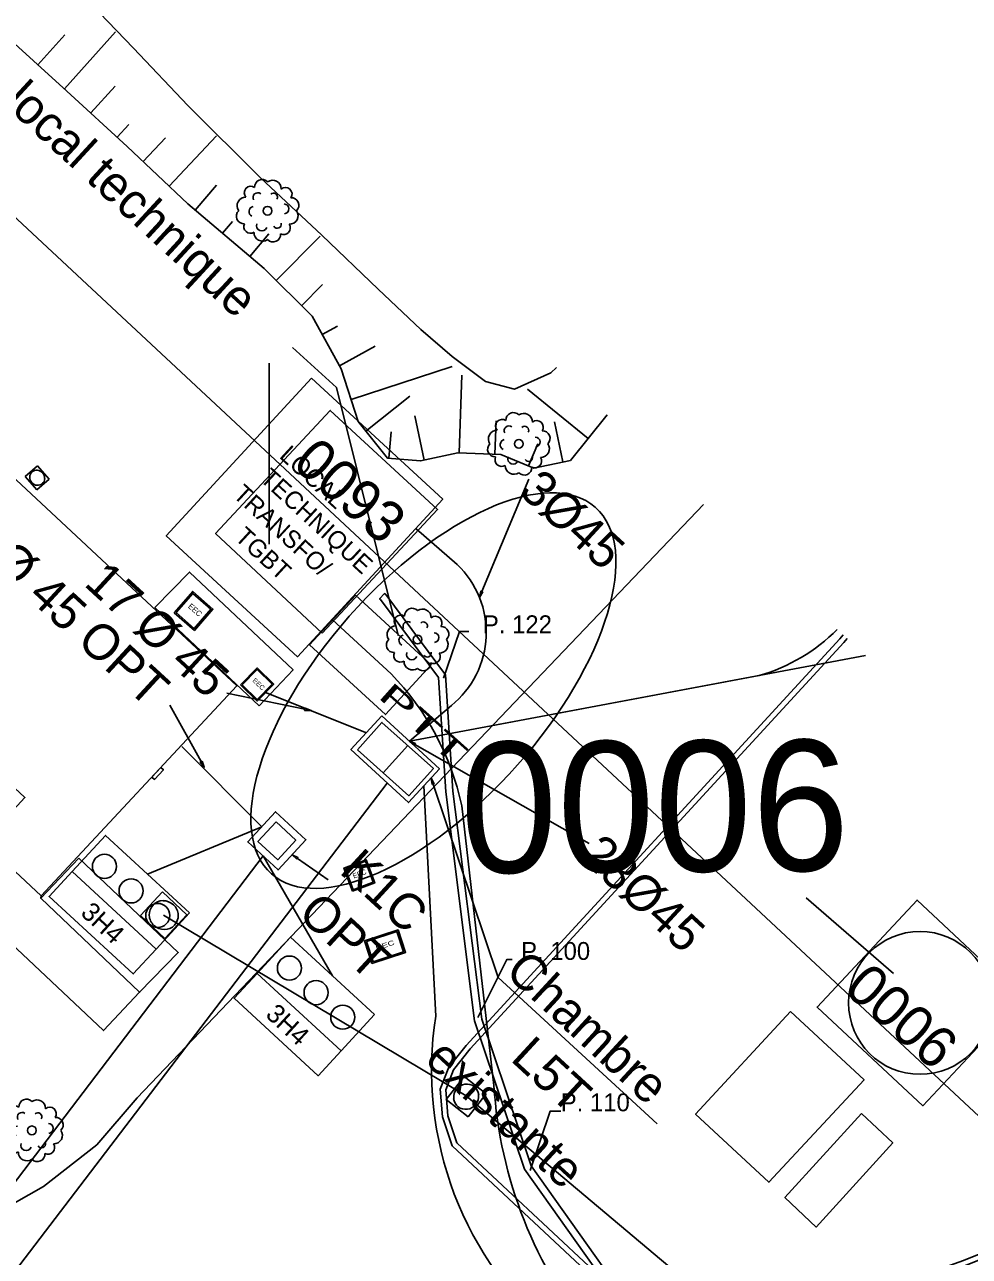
# Model space of a CAD drawing. Extents: x 343997 to 344255, y 298512 to 298767.
# Drawn here: x 344165.08 to 344191.53, y 298671.53 to 298706.03 of the extents above; entities that cross this region are included whole.
import ezdxf

# ---------------------------------------------------------------- set-up
doc = ezdxf.new("R2010")
doc.units = 0
for name, color, linetype in [('Commentaires', 7, 'Continuous'), ('Default', 7, 'Continuous'), ('DH_CADRE -CARTOUCHE', 7, 'Continuous'), ('DH_CADRE-CARTOUCHE', 7, 'Continuous'), ('DH_CADRE-CARTOUCHE-NORD', 7, 'Continuous'), ('DH_NORD', 7, 'Continuous'), ('DH_TEXTE', 7, 'Continuous'), ('DIR-Projet VRD1', 7, 'Continuous'), ('EDE - VRD - O-DONNEE', 7, 'Continuous'), ('EL-coffret', 7, 'Continuous'), ('EL-FOURR', 7, 'Continuous'), ('EL-GC', 7, 'Continuous'), ('EL-Projet VRD HTA', 7, 'Continuous'), ('GO_DALLE', 7, 'Continuous'), ('MT-DONNEE', 7, 'Continuous'), ('MT-TRANS', 7, 'Continuous'), ('O-Projet New VRD', 7, 'Continuous'), ('OPT chambre', 7, 'Continuous'), ('OPT texte', 7, 'Continuous'), ('OPT VRD', 7, 'Continuous'), ('PC_REBAR', 7, 'Continuous'), ('PS_OBJECT', 7, 'Continuous'), ('PS_PLATE', 7, 'Continuous'), ('RES_EAU PLUVIALE', 7, 'Continuous'), ('RES_ELECTRICITE', 7, 'Continuous'), ('RES_MOYENNE TENSION', 7, 'Continuous')]:
    doc.layers.add(name, color=color, linetype=linetype)

# ---------------------------------------------------------------- blocks, each defined once
blk = doc.blocks.new('CT2')
at = {"layer": 'Default'}
blk.add_lwpolyline([(0, 0), (0.1, 0), (0.1, 0.1), (0, 0.1)], close=True, dxfattribs=at)
blk.add_lwpolyline([(0.05, 0.1), (0.05, 0)], dxfattribs=at)
blk.add_text('PTT', height=0.06, dxfattribs=at).set_placement((-0.03, 0.1425))
blk = doc.blocks.new('REG_INC')
at = {"layer": 'Default'}
for p, q in [((0, 0.1), (0.1, 0.1)), ((0, 0), (0, 0.1)), ((0.1, 0.1), (0.1, 0)), ((0.1, 0), (0, 0))]:
    blk.add_line(p, q, dxfattribs=at)
for centre, start, end in [((0.0498, 0.05), 135.0055, 180.0055), ((0.05, 0.0498), 90.0058, 135.0058), ((0.05, 0.05), 45.0069, 90.0069), ((0.0499, 0.0499), 0.0066, 45.0066), ((0.0501, 0.05), 180.0066, 225.0066), ((0.0501, 0.0499), 315.0055, 0.0055), ((0.0499, 0.0498), 225.0069, 270.0069), ((0.0499, 0.05), 270.0058, 315.0058)]:
    blk.add_arc(centre, 0.044, start, end, dxfattribs=at)
blk = doc.blocks.new('RES_ELECTRICITE')
at = {"layer": 'RES_ELECTRICITE'}
for points in [[(0, 0), (0, 0.1), (0.1, 0.1), (0.1, 0)], [(0.005, 0.005), (0.005, 0.095), (0.095, 0.095), (0.095, 0.005)]]:
    blk.add_lwpolyline(points, close=True, dxfattribs=at)
blk.add_text('EEC', height=0.02, dxfattribs=at).set_placement((0.0237, 0.046))
blk = doc.blocks.new('ARB1')
at = {"layer": 'Default'}
blk.add_circle((0, 0), 0.0122, dxfattribs=at)
for centre, radius, start, end in [((-0.0153, 0.0664), 0.0211, 43.6925, 183.5969), ((0.0139, 0.0613), 0.0241, 358.4583, 125.1928), ((-0.0613, 0.0139), 0.0241, 88.4583, 215.1928), ((-0.0471, 0.0503), 0.0183, 53.9554, 222.2066), ((-0.0276, 0.037), 0.0134, 52.4396, 209.5496), ((0.0164, 0.038), 0.0112, 330.5895, 133.7127), ((0.0501, 0.0468), 0.0183, 325.1444, 131.0175), ((0.0664, 0.0153), 0.0211, 313.6925, 93.5969), ((-0.0373, -0.0024), 0.0149, 103.7092, 242.3465), ((0.0458, 0.0052), 0.0137, 276.6214, 88.967), ((0.0613, -0.0139), 0.0241, 268.4583, 35.1928), ((-0.0664, -0.0153), 0.0211, 133.6925, 273.5969), ((-0.0478, -0.0443), 0.019, 155.2243, 300.9377), ((-0.0139, -0.0613), 0.0241, 178.4583, 305.1928), ((-0.0163, -0.042), 0.0148, 159.5371, 338.1663), ((0.0153, -0.0664), 0.0211, 223.6925, 3.5969), ((0.0271, -0.038), 0.0112, 210.5895, 13.7127), ((0.0448, -0.0483), 0.0188, 243.1323, 33.0297)]:
    blk.add_arc(centre, radius, start, end, dxfattribs=at)
blk = doc.blocks.new('K1C')
at = {"layer": 'Default'}
for points in [[(35083.6085, 29821.5636), (35083.7239, 29821.5636), (35083.7239, 29821.6785), (35083.6085, 29821.6785)], [(35083.6287, 29821.6586), (35083.7037, 29821.6586), (35083.7037, 29821.5836), (35083.6287, 29821.5836)]]:
    blk.add_lwpolyline(points, close=True, dxfattribs=at)
for points in [[(35083.7037, 29821.6586), (35083.7039, 29821.6585)], [(35083.6085, 29821.5637), (35083.6087, 29821.5636)]]:
    blk.add_lwpolyline(points, dxfattribs=at)
blk = doc.blocks.new('_U58')
at = {"layer": 'EDE - VRD - O-DONNEE'}
for points in [[(0.01067, 0.01553), (-0.01067, 0.01553), (-0.01067, 0.00632), (0.01067, 0.00632)], [(-0.01067, 0.00632), (0.01067, 0.00632), (0.01067, 0), (-0.01067, 0)]]:
    blk.add_lwpolyline(points, close=True, dxfattribs=at)
for centre in [(-0.00689, 0.01114), (-0.00013, 0.01114), (0.00664, 0.01114)]:
    blk.add_circle(centre, 0.00225, dxfattribs=at)
blk.add_text('3H4', height=0.0035, dxfattribs=at).set_placement((-0.00426, 0.00143))

msp = doc.modelspace()

# ---------------------------------------------------------------- linework, layer by layer
at = {"layer": 'Commentaires'}
for points in [[(344173.808, 298695.861), (344172.584, 298696.987)], [(344175.537, 298688.921), (344173.808, 298695.861)]]:
    msp.add_lwpolyline(points, dxfattribs=at)
msp.add_lwpolyline([(344175.537, 298688.921), (344175.537, 298688.92), (344175.537, 298688.921)], close=True, dxfattribs=at)
msp.add_ellipse((344176.525, 298687.373), major_axis=(4.533, 5.134), ratio=0.458958, dxfattribs=at)
at = {"layer": 'DH_CADRE -CARTOUCHE'}
for points in [[(343997.309, 298660.673), (344147.183, 298520.807), (344245.09, 298625.72), (344095.215, 298765.586)], [(344193.026, 298678.733), (344190.231, 298675.746), (344187.264, 298678.509), (344190.065, 298681.504)]]:
    msp.add_lwpolyline(points, close=True, dxfattribs=at)
msp.add_circle((344190.148, 298678.625), 2, dxfattribs=at)
at = {"layer": 'DH_CADRE-CARTOUCHE'}
for points in [[(344122.649, 298749.916), (344119.175, 298746.216), (344104.333, 298729.921), (344103.629, 298728.425), (344103.178, 298726.908), (344102.994, 298725.349), (344103.009, 298724.152), (344103.293, 298722.366), (344103.622, 298721.156), (344104.336, 298719.642), (344105.154, 298718.475), (344128.542, 298697.099), (344156.76, 298672.229), (344158.923, 298671.699), (344160.816, 298671.605), (344163.478, 298672.279), (344165.611, 298673.484), (344167.1, 298674.65), (344168.229, 298675.97), (344184.084, 298692.584)], [(344188, 298688.93), (344187.902, 298688.824), (344177.441, 298677.433), (344176.96, 298676.824), (344176.719, 298676.211), (344176.783, 298675.437), (344177.049, 298674.626), (344182.208, 298669.797), (344182.64, 298669.601), (344183.285, 298669.47), (344184.88, 298669.638), (344186.656, 298669.899), (344187.783, 298670.119), (344189.007, 298670.475), (344190.164, 298670.82), (344191.42, 298671.271), (344192.391, 298671.666), (344193.259, 298672.085), (344195.097, 298672.911), (344197.862, 298674.128), (344198.708, 298674.569), (344199.685, 298675.181), (344198.697, 298676.128)], [(344188.109, 298688.828), (344188.012, 298688.722), (344177.555, 298677.336), (344177.092, 298676.749), (344176.872, 298676.188), (344176.931, 298675.467), (344177.18, 298674.709), (344182.292, 298669.924), (344182.687, 298669.745), (344183.293, 298669.621), (344184.862, 298669.787), (344186.631, 298670.046), (344187.747, 298670.264), (344188.964, 298670.619), (344190.117, 298670.962), (344191.366, 298671.411), (344192.331, 298671.803), (344193.196, 298672.221), (344195.036, 298673.048), (344197.797, 298674.263), (344198.633, 298674.699), (344199.442, 298675.206), (344198.593, 298676.019), (344198.697, 298676.128)]]:
    msp.add_lwpolyline(points, dxfattribs=at)
at = {"layer": 'DH_CADRE-CARTOUCHE-NORD'}
for points in [[(344166.599, 298682.682), (344169.384, 298680.035), (344168.3, 298678.926), (344165.531, 298681.558)], [(344166.599, 298682.682), (344165.531, 298681.558)], [(344237.935, 298621.298), (344195.027, 298661.228), (344177.442, 298676.027), (344168.974, 298681.087)]]:
    msp.add_lwpolyline(points, dxfattribs=at)
at = {"layer": 'DH_TEXTE'}
for p, q in [((344171.924, 298696.541), (344171.924, 298691.473)), ((344186.963, 298681.569), (344189.41, 298679.451))]:
    msp.add_line(p, q, dxfattribs=at)
at = {"layer": 'DIR-Projet VRD1'}
for p, q in [((344188.618, 298688.353), (344175.853, 298685.953)), ((344175.853, 298685.953), (344185.645, 298687.794)), ((344175.232, 298684.784), (344162.44, 298668.004))]:
    msp.add_line(p, q, dxfattribs=at)
for points in [[(344176.047, 298691.903), (344177.193, 298690.9)], [(344174.649, 298686.191), (344171.827, 298687.323)], [(344177.029, 298686.955), (344175.853, 298685.953)], [(344176.26, 298684.707), (344176.591, 298678.258)]]:
    msp.add_lwpolyline(points, dxfattribs=at)
for centre, radius, start, end in [((344175.379, 298689), 2.627, 308.9097, 46.3418), ((344184.276, 298692.607), 5.003, 285.8756, 315.2875), ((344186.231, 298676.743), 9.758, 171.0714, 230.5902)]:
    msp.add_arc(centre, radius, start, end, dxfattribs=at)
at = {"layer": 'EL-coffret'}
msp.add_lwpolyline([(344168.896, 298685.223), (344168.968, 298685.156), (344168.718, 298684.884), (344168.645, 298684.951)], close=True, dxfattribs=at)
at = {"layer": 'EL-FOURR'}
msp.add_lwpolyline([(344182.92, 298668.55), (344179.08, 298673.97), (344177.68, 298678.12), (344176.87, 298684.54), (344176.67, 298687.74), (344175.04, 298689.92), (344175.02, 298689.94), (344175.16, 298690.09), (344175.19, 298690.06), (344176.86, 298687.81), (344177.07, 298684.56), (344177.88, 298678.17), (344179.26, 298674.06), (344183.08, 298668.68)], dxfattribs=at)
at = {"layer": 'EL-GC'}
msp.add_lwpolyline([(344173.11, 298696.12), (344176.789, 298692.734), (344172.725, 298688.319), (344169.046, 298691.706)], close=True, dxfattribs=at)
at = {"layer": 'EL-Projet VRD HTA'}
msp.add_lwpolyline([(344174.342, 298690.05), (344176.465, 298688.096), (344175.183, 298686.703), (344173.06, 298688.657)], close=True, dxfattribs=at)
at = {"layer": 'GO_DALLE'}
msp.add_lwpolyline([(344165.544, 298681.621), (344165.531, 298681.558), (344168.3, 298678.926), (344167.289, 298677.848), (344153.365, 298690.972), (344139.141, 298704.253), (344140.184, 298705.334)], dxfattribs=at)
for points in [[(344171.646, 298686.945), (344168.73, 298689.7), (344169.697, 298690.692), (344172.598, 298687.952)], [(344186.526, 298678.381), (344188.581, 298676.471), (344185.918, 298673.601), (344183.863, 298675.512)], [(344188.509, 298675.532), (344189.384, 298674.705), (344187.243, 298672.345), (344186.368, 298673.172)]]:
    msp.add_lwpolyline(points, close=True, dxfattribs=at)
at = {"layer": 'MT-DONNEE'}
for points in [[(344176.81, 298687.72), (344177.26, 298689.03), (344177.52, 298689.03)], [(344177.77, 298678.22), (344178.58, 298679.84), (344178.73, 298679.84)], [(344179.23, 298673.93), (344179.79, 298675.59), (344180.09, 298675.59)]]:
    msp.add_lwpolyline(points, dxfattribs=at)
at = {"layer": 'MT-TRANS'}
msp.add_lwpolyline([(344173.412, 298688.979), (344170.426, 298691.775), (344173.636, 298695.222), (344176.642, 298692.441)], close=True, dxfattribs=at)
at = {"layer": 'O-Projet New VRD'}
for points in [[(344177.885, 298690.149), (344179.199, 298693.297)], [(344172.924, 298686.849), (344170.744, 298687.299)], [(344176.009, 298685.864), (344180.887, 298683.091)], [(344176.517, 298684.754), (344178.341, 298679.334)], [(344178.341, 298679.334), (344182.793, 298675.235)]]:
    msp.add_lwpolyline(points, dxfattribs=at)
for points in [[(344177.913, 298690.138), (344177.816, 298689.983), (344177.857, 298690.161)], [(344172.931, 298686.878), (344173.101, 298686.812), (344172.918, 298686.819)], [(344175.083, 298686.662), (344176.694, 298685.178), (344175.827, 298684.237), (344174.216, 298685.72)], [(344175.994, 298685.838), (344175.853, 298685.953), (344176.024, 298685.89)], [(344176.489, 298684.744), (344176.46, 298684.924), (344176.546, 298684.763)]]:
    msp.add_lwpolyline(points, close=True, dxfattribs=at)
at = {"layer": 'OPT chambre'}
msp.add_lwpolyline([(344172.674, 298683.188), (344172.675, 298683.186)], dxfattribs=at)
at = {"layer": 'OPT texte'}
for points in [[(344170.025, 298685.383), (344169.144, 298686.96)], [(344168.523, 298682.234), (344171.72, 298683.556)], [(344173.701, 298679.385), (344171.755, 298682.743)], [(344172.717, 298682.673), (344173.581, 298682.076)]]:
    msp.add_lwpolyline(points, dxfattribs=at)
for points in [[(344170.051, 298685.398), (344170.112, 298685.226), (344169.998, 298685.369)], [(344172.7, 298682.648), (344172.568, 298682.775), (344172.734, 298682.697)]]:
    msp.add_lwpolyline(points, close=True, dxfattribs=at)
at = {"layer": 'OPT VRD'}
msp.add_line((344171.72, 298683.556), (344169.486, 298685.809), dxfattribs=at)
msp.add_lwpolyline([(344171.755, 298682.743), (344159.176, 298666.214)], dxfattribs=at)
at = {"layer": 'PS_OBJECT'}
for p, q in [((344166.194, 298704.228), (344167.63, 298705.819)), ((344165.452, 298704.899), (344166.207, 298705.736)), ((344166.931, 298703.552), (344167.62, 298704.301)), ((344167.668, 298702.875), (344167.995, 298703.231)), ((344168.398, 298702.192), (344169.029, 298702.858)), ((344169.124, 298701.504), (344170.456, 298702.91)), ((344169.86, 298700.827), (344170.455, 298701.528)), ((344170.623, 298700.18), (344170.905, 298700.513)), ((344171.385, 298699.533), (344171.922, 298700.165)), ((344172.123, 298698.858), (344173.356, 298700.101)), ((344172.833, 298698.154), (344173.419, 298698.744)), ((344173.41, 298697.349), (344173.837, 298697.584)), ((344173.893, 298696.473), (344174.893, 298697.024)), ((344174.22, 298695.529), (344177.051, 298696.448)), ((344177.249, 298694.03), (344177.324, 298696.208)), ((344180.856, 298694.434), (344179.157, 298695.812)), ((344174.638, 298694.637), (344175.866, 298695.615)), ((344176.27, 298693.827), (344176.001, 298695.073)), ((344178.249, 298693.996), (344178.281, 298694.927)), ((344180.152, 298693.778), (344179.912, 298694.904)), ((344175.276, 298693.882), (344175.34, 298694.624)), ((344179.184, 298693.667), (344179.445, 298694.288))]:
    msp.add_line(p, q, dxfattribs=at)
for points in [[(344148.445, 298717.676), (344150.54, 298719.466), (344152.414, 298719.731), (344154.52, 298718.736), (344157.154, 298716.789), (344159.618, 298714.441), (344161.857, 298712.179), (344163.938, 298709.792), (344165.996, 298707.602), (344168.133, 298705.364), (344169.649, 298703.764), (344171.689, 298701.731), (344173.402, 298700.124), (344174.981, 298698.62), (344176.175, 298697.484), (344177.055, 298696.727), (344177.983, 298696.033), (344178.792, 298695.819), (344179.816, 298696.274), (344179.969, 298696.425)], [(344181.393, 298695.096), (344180.359, 298693.822), (344179.336, 298693.603), (344178.417, 298693.99), (344177.213, 298694.032), (344176.166, 298693.805), (344175.237, 298693.885), (344174.421, 298694.91), (344173.943, 298696.382), (344173.127, 298697.863), (344171.784, 298699.194), (344169.649, 298701.006), (344167.952, 298702.614), (344166.263, 298704.166), (344164.386, 298705.861), (344162.327, 298707.753), (344160.411, 298709.58), (344158.416, 298711.503), (344156.776, 298713.133), (344155.261, 298714.653), (344154.185, 298715.701), (344152.74, 298717.04), (344151.828, 298717.703), (344151.113, 298717.994)]]:
    msp.add_lwpolyline(points, dxfattribs=at)
at = {"layer": 'PS_PLATE'}
msp.add_lwpolyline([(344163.929, 298683.13), (344165.092, 298684.375), (344155.123, 298693.692), (344153.96, 298692.447), (344140.184, 298705.334), (344145.624, 298711.233), (344171.024, 298687.508), (344165.544, 298681.621)], close=True, dxfattribs=at)
at = {"layer": 'RES_MOYENNE TENSION'}
for p, q in [((344173.701, 298689.354), (344175.339, 298687.841)), ((344177.319, 298684.148), (344178.219, 298676.309))]:
    msp.add_line(p, q, dxfattribs=at)
for centre, radius, start, end in [((344169.898, 298682.548), 7.591, 12.1658, 44.2073), ((344190.578, 298677.102), 12.385, 183.6707, 219.5408)]:
    msp.add_arc(centre, radius, start, end, dxfattribs=at)

# ---------------------------------------------------------------- block references
at = {"layer": 'DH_NORD', "xscale": 19.321527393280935, "yscale": 10.29208284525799, "rotation": -41.79393776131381}
msp.add_blockref('CT2', (344174.399, 298685.715), dxfattribs=at)
at = {"layer": 'OPT chambre', "xscale": 10, "yscale": 10, "rotation": -42.63277399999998}
msp.add_blockref('K1C', (-115922.741, 316903.171), dxfattribs=at)
at = {"layer": 'OPT texte', "xscale": 150, "yscale": 150, "rotation": -42.63277399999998}
for p in [(344166.945, 298680.52), (344172.123, 298677.671)]:
    msp.add_blockref('_U58', p, dxfattribs=at)
at = {"layer": 'PC_REBAR', "xscale": 10, "yscale": 10}
for p in [(344171.884, 298700.814), (344178.918, 298694.284), (344176.083, 298688.804), (344165.286, 298675.056)]:
    msp.add_blockref('ARB1', p, dxfattribs=at)
at = {"layer": 'RES_EAU PLUVIALE'}
for p, xscale, yscale, rotation in [((344165.77, 298693.299), 4.60571420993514, -4.9462206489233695, -138.83616000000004), ((344169.626, 298681.093), 9.35414063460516, 9.050997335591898, 136.74329999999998), ((344178.003, 298676.077), 7.87015340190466, 8.16746639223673, 141.88994999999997)]:
    msp.add_blockref('REG_INC', p, dxfattribs=dict(at, xscale=xscale, yscale=yscale, rotation=rotation))
at = {"layer": 'RES_ELECTRICITE'}
for p, xscale, yscale, rotation in [((344169.268, 298689.555), 7.507731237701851, 7.89093981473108, -41.21122458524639), ((344171.124, 298687.531), 6.49637960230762, 6.661458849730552, -44.13421264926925), ((344174.263, 298681.752), 6.634214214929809, 6.95493592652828, 20.56731581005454), ((344174.803, 298679.732), 9.9024213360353, 6.61972410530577, 18.125818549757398)]:
    msp.add_blockref('RES_ELECTRICITE', p, dxfattribs=dict(at, xscale=xscale, yscale=yscale, rotation=rotation))

# ---------------------------------------------------------------- texts
at = {"layer": 'Commentaires'}
msp.add_text('Fausse chambre pour entrée câble HTA dans local technique', height=1.00027, rotation=317.3672, dxfattribs=at).set_placement((344144.279, 298722.385))
at = {"layer": 'DH_TEXTE'}
for s, height, rotation, p in [('0093', 1.1492, 318.6191, (344172.533, 298693.68)), ('0006', 3.662, 0.3665, (344177.282, 298682.264)), ('0006', 1.1492, 318.6191, (344187.983, 298678.958))]:
    msp.add_text(s, height=height, rotation=rotation, dxfattribs=at).set_placement(p)
at = {"layer": 'EL-GC'}
for s, p in [('LOCAL', (344172.185, 298693.915)), ('TECHNIQUE', (344171.64, 298693.272)), ('TRANSFO/', (344170.889, 298692.819)), ('TGBT', (344170.937, 298691.63))]:
    msp.add_text(s, height=0.5, rotation=317.3672, dxfattribs=at).set_placement(p)
at = {"layer": 'MT-DONNEE'}
for s, p in [('P. 122', (344177.91, 298688.98)), ('P. 100', (344178.98, 298679.83)), ('P. 110', (344180.09, 298675.59))]:
    msp.add_text(s, height=0.5, dxfattribs=at).set_placement(p)
at = {"layer": 'O-Projet New VRD'}
for s, p in [('3Ø45', (344178.884, 298692.909)), ('17 Ø 45', (344166.714, 298690.334)), ('23Ø45', (344180.585, 298682.691)), ('Chambre', (344178.491, 298679.445)), ('L5T', (344178.652, 298677.03)), ('existante', (344176.24, 298676.985))]:
    msp.add_text(s, height=1.0003, rotation=317.3672, dxfattribs=at).set_placement(p)
at = {"layer": 'OPT texte'}
for s, p in [('3 Ø 45 OPT', (344163.278, 298691.686)), ('K1C', (344173.863, 298682.282)), ('OPT', (344172.694, 298681.069))]:
    msp.add_text(s, height=1.0003, rotation=317.3672, dxfattribs=at).set_placement(p)

doc.saveas('drawing.dxf')
